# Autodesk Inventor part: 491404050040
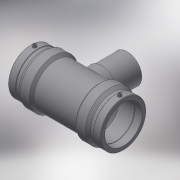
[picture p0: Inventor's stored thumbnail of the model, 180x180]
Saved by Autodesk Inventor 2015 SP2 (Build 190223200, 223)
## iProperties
Created: 2017-06
Part Number: 491404050040
Material: Generic
Description: PLASSON REDUCING TEE 50x40x50
Document SubType Name: Modeling
Designer: KIM
Mass: 244.008 g
Surface Area: 693.346 cm^2
Volume: 244.008 cm^3
Density: 1 g/cm^3
Appearance: Default
Author: KIM
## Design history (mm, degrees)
derived "491404.ipt"
feature "Solid1::491404.ipt"
tag "TaggingFeature1"
body "Solid1"
other parameters: "d0" = 139, "d2" = 68, "d3" = 48, "d4" = 27.8, "d5" = 61.2, "d6" = 47.5, "d8" = 168 deg, "d10" = 19.2, "d11" = 6.4, "d13" = 139, "d14" = 17.6296, "d17" = 45, "d19" = 3.52592, "d20" = 168 deg, "d22" = 63.24, "d23" = 68, "d25" = 135 deg, "d26" = 97.3, "d29" = 52, "d30" = 15, "d31" = 55.6, "d34" = 5 deg, "d35" = 15, "d39" = 5 deg, "d41" = 4, "d42" = 14, "d43" = 0, "d45" = 4, "d46" = 6, "d47" = 0, "d51" = 0, "d52" = 32, "d54" = 0, "d55" = 61.2, "d56" = 68, "d57" = 48.65, "d58" = 135 deg, "d59" = 48, "d60" = 48, "d61" = 135 deg, "d72" = 63.245, "d73" = 31.6225, "d75" = 42, "d77" = 0, "d78" = 32, "d80" = 0, "d82" = 56, "d83" = 0, "d84" = 3, "d85" = 0, "d86" = 16, "d87" = 61.9752, "d88" = 6.4, "d89" = 3, "d90" = 0, "L_" = 139, "L_1" = 48, "D_" = 68, "A_" = 52, "d_2" = 12
